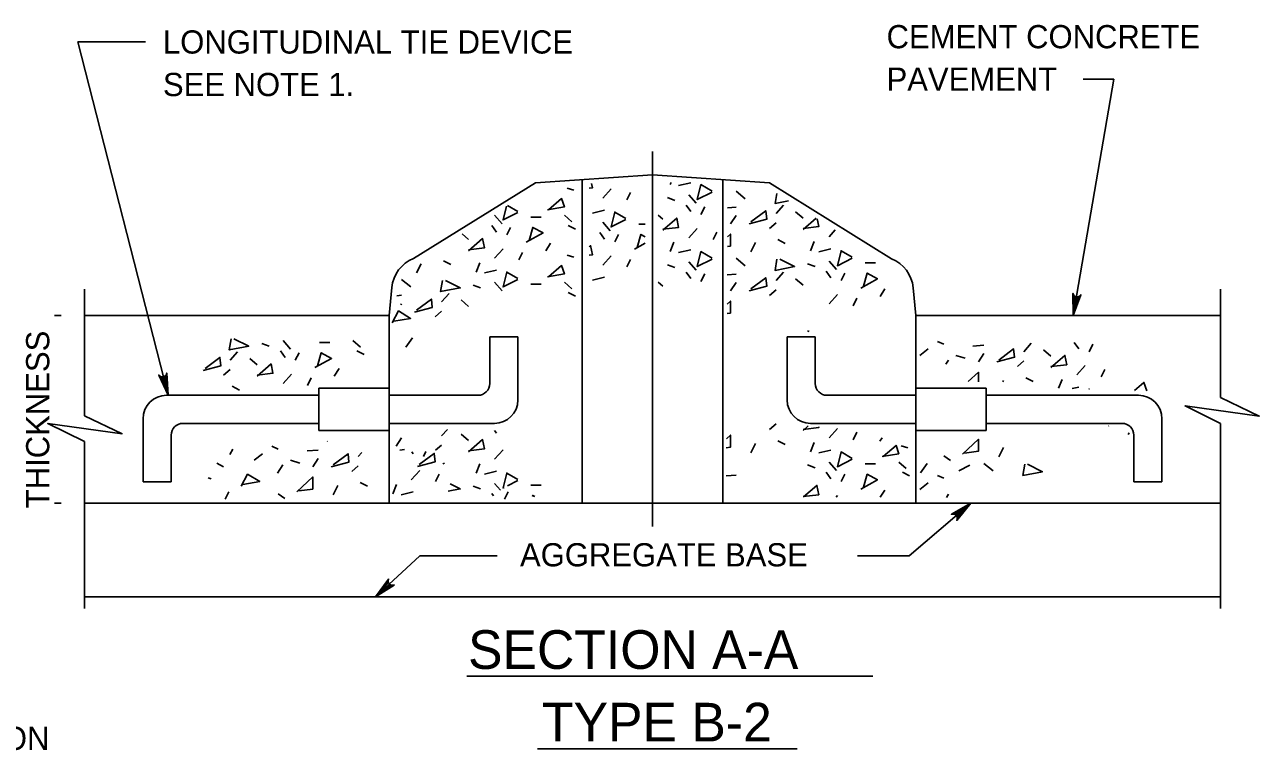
# Model space of a CAD drawing. Extents: x -7.6 to -0.4, y 98.1 to 108.3.
# Drawn here: x -3.651 to -0.457, y 106.268 to 108.145 of the extents above; entities that cross this region are included whole.
import ezdxf

# ---------------------------------------------------------------- set-up
doc = ezdxf.new("R2010")
doc.units = 0
for name, color, linetype in [('DETL-DIMS', 7, 'Continuous'), ('DETL-LINE', 7, 'Continuous'), ('DETL-NOTE', 7, 'Continuous'), ('DETL-PATT', 7, 'Continuous'), ('DETL-TITL', 7, 'Continuous')]:
    doc.layers.add(name, color=color, linetype=linetype)

msp = doc.modelspace()

# ---------------------------------------------------------------- linework, layer by layer
at = {"layer": 'DETL-DIMS'}
for p, q in [((-3.5134, 108.1001), (-3.2795, 107.1864)), ((-3.5134, 108.1001), (-3.3386, 108.1001)), ((-0.833, 108.0038), (-0.9381, 107.3925)), ((-0.9126, 108.0038), (-0.833, 108.0038)), ((-2.0265, 106.847), (-2.0265, 107.8167)), ((-3.5567, 107.3925), (-3.5738, 107.3925)), ((-3.5738, 106.9076), (-3.5567, 106.9076)), ((-1.3625, 106.771), (-1.2032, 106.9076)), ((-2.6289, 106.771), (-2.7435, 106.6652)), ((-2.428, 106.771), (-2.6289, 106.771)), ((-1.4964, 106.771), (-1.3625, 106.771))]:
    msp.add_line(p, q, dxfattribs=at)
for points in [[(-0.9381, 107.3925), (-0.9389, 107.45), (-0.9367, 107.4452), (-0.9334, 107.4423), (-0.9297, 107.441), (-0.9259, 107.441), (-0.9218, 107.4426), (-0.9181, 107.4464), (-0.9381, 107.3925), (-0.9218, 107.4426), (-0.9259, 107.441), (-0.9381, 107.3925), (-0.9297, 107.441), (-0.9334, 107.4423), (-0.9381, 107.3925), (-0.9367, 107.4452)], [(-3.2795, 107.1864), (-3.3038, 107.2385), (-3.2998, 107.2351), (-3.2955, 107.2338), (-3.2917, 107.2341), (-3.2882, 107.2357), (-3.2851, 107.2388), (-3.2832, 107.2438), (-3.2795, 107.1864), (-3.2851, 107.2388), (-3.2882, 107.2357), (-3.2795, 107.1864), (-3.2917, 107.2341), (-3.2955, 107.2338), (-3.2795, 107.1864), (-3.2998, 107.2351)], [(-1.2032, 106.9076), (-1.2392, 106.8628), (-1.2379, 106.8679), (-1.2387, 106.8723), (-1.2406, 106.8756), (-1.2436, 106.878), (-1.2477, 106.8794), (-1.253, 106.8789), (-1.2032, 106.9076), (-1.2477, 106.8794), (-1.2436, 106.878), (-1.2032, 106.9076), (-1.2406, 106.8756), (-1.2387, 106.8723), (-1.2032, 106.9076), (-1.2379, 106.8679)], [(-2.7435, 106.6652), (-2.7092, 106.7113), (-2.7104, 106.7062), (-2.7094, 106.7018), (-2.7073, 106.6986), (-2.7043, 106.6963), (-2.7001, 106.695), (-2.6948, 106.6958), (-2.7435, 106.6652), (-2.7001, 106.695), (-2.7043, 106.6963), (-2.7435, 106.6652), (-2.7073, 106.6986), (-2.7094, 106.7018), (-2.7435, 106.6652), (-2.7104, 106.7062)]]:
    msp.add_lwpolyline(points, dxfattribs=at)
at = {"layer": 'DETL-LINE'}
for p, q in [((-2.3295, 107.7359), (-2.0265, 107.7561)), ((-2.2083, 106.9076), (-2.2083, 107.744)), ((-1.7235, 107.7359), (-2.0265, 107.7561)), ((-1.8447, 106.9076), (-1.8447, 107.744)), ((-2.3295, 107.7359), (-2.645, 107.5404)), ((-1.7235, 107.7359), (-1.4079, 107.5396)), ((-3.4961, 107.4608), (-3.4961, 107.1332)), ((-2.7082, 107.3925), (-2.701, 107.4653)), ((-1.3448, 107.3925), (-1.352, 107.4645)), ((-0.5569, 107.4608), (-0.5569, 107.1804)), ((-3.4961, 107.3925), (-2.7082, 107.3925)), ((-2.7082, 107.3925), (-2.7082, 106.9076)), ((-1.3448, 107.3925), (-0.5569, 107.3925)), ((-1.3448, 107.3925), (-1.3448, 106.9076)), ((-2.4476, 107.3379), (-2.4476, 107.2167)), ((-2.4476, 107.3379), (-2.3749, 107.3379)), ((-2.3749, 107.3379), (-2.3749, 107.1743)), ((-1.6781, 107.3379), (-1.6781, 107.1743)), ((-1.6054, 107.3379), (-1.6781, 107.3379)), ((-1.6054, 107.3379), (-1.6054, 107.2167)), ((-2.7082, 107.2046), (-2.8901, 107.2046)), ((-2.8901, 107.2046), (-2.8901, 107.0955)), ((-1.3448, 107.2228), (-1.3448, 107.0773)), ((-1.3448, 107.2046), (-1.163, 107.2046)), ((-1.163, 107.2046), (-1.163, 107.0955)), ((-3.284, 107.1864), (-2.8901, 107.1864)), ((-2.7082, 107.1864), (-2.4779, 107.1864)), ((-1.3448, 107.1864), (-1.5751, 107.1864)), ((-0.769, 107.1864), (-1.163, 107.1864)), ((-3.3446, 107.1258), (-3.3446, 106.9622)), ((-3.2416, 107.1137), (-2.8901, 107.1137)), ((-2.7082, 107.1137), (-2.4355, 107.1137)), ((-1.3448, 107.1137), (-1.6175, 107.1137)), ((-0.8115, 107.1137), (-1.163, 107.1137)), ((-0.7084, 107.1258), (-0.7084, 106.9622)), ((-0.5569, 107.1138), (-0.5569, 106.6353)), ((-3.2719, 107.0834), (-3.2719, 106.9622)), ((-2.7082, 107.0955), (-2.8901, 107.0955)), ((-1.3448, 107.0955), (-1.163, 107.0955)), ((-0.7812, 107.0834), (-0.7812, 106.9622)), ((-3.4961, 107.0666), (-3.4961, 106.6353)), ((-2.7082, 107.0289), (-2.7082, 106.9076)), ((-1.3448, 107.0289), (-1.3448, 106.9076)), ((-3.3446, 106.9622), (-3.2719, 106.9622)), ((-0.7084, 106.9622), (-0.7812, 106.9622)), ((-3.4961, 106.9076), (-0.5569, 106.9076)), ((-3.4961, 106.6652), (-0.5569, 106.6652))]:
    msp.add_line(p, q, dxfattribs=at)
for points in [[(-0.5569, 107.1138), (-0.6488, 107.1588), (-0.4566, 107.1326), (-0.5569, 107.1804)], [(-3.4961, 107.0666), (-3.5913, 107.1131), (-3.399, 107.087), (-3.4961, 107.1332)]]:
    msp.add_lwpolyline(points, dxfattribs=at)
for centre, radius, start, end in [((-2.6105, 107.4562), 0.0909, 112.2917, 174.2894), ((-1.4425, 107.4555), 0.0909, 5.7107, 67.6341), ((-2.4779, 107.2167), 0.0303, 270, 0), ((-1.5751, 107.2167), 0.0303, 180, 270), ((-3.284, 107.1258), 0.0606, 90, 180), ((-2.4355, 107.1743), 0.0606, 270, 0), ((-1.6175, 107.1743), 0.0606, 180, 270), ((-0.769, 107.1258), 0.0606, 0, 90), ((-3.2416, 107.0834), 0.0303, 90, 180), ((-0.8115, 107.0834), 0.0303, 0, 90)]:
    msp.add_arc(centre, radius, start, end, dxfattribs=at)
at = {"layer": 'DETL-PATT'}
for p, q in [((-2.2472, 107.7217), (-2.2304, 107.7169)), ((-2.1337, 107.7204), (-2.1553, 107.6963)), ((-2.0831, 107.7108), (-2.0928, 107.6915)), ((-1.9785, 107.7364), (-1.9806, 107.7312)), ((-1.9276, 107.736), (-1.9589, 107.7288)), ((-1.8104, 107.7141), (-1.7864, 107.6948)), ((-1.9878, 107.6975), (-1.9685, 107.6903)), ((-1.9397, 107.6783), (-1.9276, 107.6614)), ((-1.9324, 107.7047), (-1.9132, 107.6831)), ((-1.7069, 107.6563), (-1.6877, 107.6779)), ((-2.435, 107.6519), (-2.4157, 107.6302)), ((-2.4014, 107.6771), (-2.3748, 107.6615)), ((-2.3411, 107.6471), (-2.3146, 107.6471)), ((-2.2545, 107.6519), (-2.2352, 107.6351)), ((-2.1505, 107.665), (-2.1818, 107.6578)), ((-2.0117, 107.6526), (-1.9998, 107.6422)), ((-1.8915, 107.6734), (-1.9012, 107.6542)), ((-1.8322, 107.6713), (-1.8104, 107.6731)), ((-1.8249, 107.6298), (-1.8104, 107.6515)), ((-1.6564, 107.6611), (-1.6371, 107.6443)), ((-2.4422, 107.6254), (-2.4302, 107.6086)), ((-2.3941, 107.6206), (-2.4037, 107.6014)), ((-2.2448, 107.6254), (-2.2256, 107.6158)), ((-2.1553, 107.6337), (-2.1361, 107.6121)), ((-2.0615, 107.6289), (-2.0454, 107.6289)), ((-1.9108, 107.6181), (-1.9324, 107.594)), ((-1.7238, 107.6178), (-1.7069, 107.6322)), ((-1.6032, 107.6448), (-1.6371, 107.6154)), ((-1.5537, 107.6139), (-1.5697, 107.5961)), ((-2.5187, 107.6036), (-2.5024, 107.5893)), ((-2.1625, 107.6073), (-2.1505, 107.5904)), ((-2.1144, 107.6024), (-2.124, 107.5832)), ((-1.9709, 107.582), (-1.9806, 107.5579)), ((-1.8602, 107.6085), (-1.8699, 107.5892)), ((-1.7021, 107.5889), (-1.6829, 107.5793)), ((-1.6082, 107.5841), (-1.6179, 107.56)), ((-2.4133, 107.5653), (-2.435, 107.5412)), ((-2.3628, 107.5556), (-2.3724, 107.5364)), ((-2.3026, 107.5604), (-2.2906, 107.5797)), ((-2.0735, 107.5639), (-2.0454, 107.5796)), ((-1.9276, 107.5627), (-1.9589, 107.5555)), ((-1.7719, 107.5576), (-1.7599, 107.5817)), ((-1.5649, 107.5648), (-1.5962, 107.5576)), ((-2.6372, 107.5027), (-2.6251, 107.5267)), ((-2.5674, 107.534), (-2.5481, 107.5243)), ((-2.4735, 107.5292), (-2.4831, 107.5051)), ((-2.2472, 107.5484), (-2.2304, 107.5436)), ((-2.1337, 107.5471), (-2.1553, 107.523)), ((-2.0831, 107.5375), (-2.0928, 107.5182)), ((-1.9878, 107.5242), (-1.9685, 107.517)), ((-1.9324, 107.5314), (-1.9132, 107.5098)), ((-1.8104, 107.5408), (-1.7864, 107.5215)), ((-1.6251, 107.5263), (-1.6058, 107.5191)), ((-1.5697, 107.5336), (-1.5505, 107.5119)), ((-1.4759, 107.5287), (-1.4494, 107.5287)), ((-2.4302, 107.5099), (-2.4615, 107.5027)), ((-2.1505, 107.4917), (-2.1818, 107.4845)), ((-1.9397, 107.505), (-1.9276, 107.4881)), ((-1.8915, 107.5002), (-1.9012, 107.4809)), ((-1.8331, 107.4979), (-1.8104, 107.4998)), ((-1.7069, 107.483), (-1.6877, 107.5047)), ((-1.6564, 107.4878), (-1.6371, 107.471)), ((-1.5769, 107.5071), (-1.5649, 107.4902)), ((-1.5288, 107.5023), (-1.5384, 107.483)), ((-2.6757, 107.4858), (-2.6516, 107.4666)), ((-2.4903, 107.4714), (-2.4711, 107.4642)), ((-2.435, 107.4786), (-2.4157, 107.4569)), ((-2.3411, 107.4738), (-2.3146, 107.4738)), ((-2.2545, 107.4786), (-2.2352, 107.4618)), ((-2.0117, 107.4792), (-1.9998, 107.4689)), ((-1.8249, 107.4565), (-1.8104, 107.4782)), ((-1.7238, 107.4445), (-1.7069, 107.4589)), ((-1.4374, 107.4421), (-1.4253, 107.4613)), ((-2.6884, 107.4438), (-2.6757, 107.4449)), ((-2.6774, 107.4206), (-2.6757, 107.4232)), ((-2.5722, 107.4281), (-2.5529, 107.4497)), ((-2.5216, 107.4329), (-2.5024, 107.416)), ((-2.2448, 107.4521), (-2.2256, 107.4425)), ((-1.5481, 107.4469), (-1.5697, 107.4228)), ((-1.4975, 107.4373), (-1.5072, 107.418)), ((-2.589, 107.3896), (-2.5722, 107.404)), ((-2.982, 107.3277), (-2.9628, 107.306)), ((-2.8015, 107.3277), (-2.7823, 107.3108)), ((-2.6475, 107.3349), (-2.6643, 107.3108)), ((-1.6251, 107.353), (-1.6209, 107.3514)), ((-3.1192, 107.2771), (-3.1, 107.2988)), ((-3.0374, 107.3204), (-3.0181, 107.3132)), ((-2.9893, 107.3012), (-2.9772, 107.2843)), ((-2.9411, 107.2964), (-2.9507, 107.2771)), ((-2.8882, 107.3228), (-2.8617, 107.3228)), ((-2.7919, 107.3012), (-2.7726, 107.2916)), ((-1.3135, 107.3064), (-1.3352, 107.2896)), ((-1.2894, 107.3257), (-1.2726, 107.3184)), ((-1.198, 107.3136), (-1.1691, 107.316)), ((-1.0656, 107.2992), (-1.0464, 107.3208)), ((-1.0151, 107.304), (-0.9958, 107.2872)), ((-0.9356, 107.3233), (-0.9236, 107.3064)), ((-0.8875, 107.3184), (-0.8971, 107.2992)), ((-3.0687, 107.2819), (-3.0494, 107.2651)), ((-1.2606, 107.2775), (-1.2678, 107.2666)), ((-1.2413, 107.2896), (-1.2172, 107.2823)), ((-1.1835, 107.2727), (-1.1691, 107.2944)), ((-1.0825, 107.2607), (-1.0656, 107.2751)), ((-0.9068, 107.2631), (-0.9284, 107.239)), ((-3.1361, 107.2386), (-3.1192, 107.2531)), ((-2.9604, 107.241), (-2.982, 107.2169)), ((-2.9098, 107.2314), (-2.9194, 107.2121)), ((-2.8497, 107.2362), (-2.8376, 107.2554)), ((-1.0608, 107.2318), (-1.0415, 107.2222)), ((-0.8562, 107.2534), (-0.8658, 107.2342)), ((-3.1144, 107.2097), (-3.0952, 107.2001)), ((-1.1203, 107.221), (-1.1186, 107.2246)), ((-0.9669, 107.227), (-0.9758, 107.2048)), ((-0.9236, 107.2077), (-0.9406, 107.2038)), ((-1.7238, 107.0979), (-1.7069, 107.1123)), ((-1.6238, 107.1071), (-1.6371, 107.0955)), ((-0.8466, 107.1066), (-0.8458, 107.1071)), ((-2.6901, 107.055), (-2.6757, 107.0767)), ((-2.5722, 107.0815), (-2.5573, 107.0982)), ((-2.5216, 107.0863), (-2.5024, 107.0694)), ((-2.435, 107.0955), (-2.4302, 107.0887)), ((-1.5481, 107.1003), (-1.5697, 107.0762)), ((-1.4975, 107.0907), (-1.5072, 107.0714)), ((-1.4383, 107.0677), (-1.4326, 107.0768)), ((-0.796, 107.085), (-0.7933, 107.0893)), ((-3.1198, 107.0329), (-3.112, 107.0467)), ((-3.0115, 107.0546), (-2.9947, 107.0474)), ((-2.9201, 107.0426), (-2.8912, 107.0449)), ((-2.8683, 107.0676), (-2.8671, 107.0666)), ((-2.68, 107.0449), (-2.6683, 107.0459)), ((-2.6492, 107.0402), (-2.6457, 107.0353)), ((-2.6129, 107.0408), (-2.6192, 107.0281)), ((-2.5876, 107.0442), (-2.5722, 107.0574)), ((-2.4133, 107.0454), (-2.435, 107.0213)), ((-1.7719, 107.0377), (-1.7599, 107.0618)), ((-1.7021, 107.069), (-1.6829, 107.0594)), ((-1.6082, 107.0642), (-1.6179, 107.0401)), ((-1.5649, 107.0449), (-1.5962, 107.0377)), ((-1.3829, 107.0556), (-1.3661, 107.0508)), ((-1.1306, 107.0272), (-1.1186, 107.0513)), ((-3.1535, 107.0113), (-3.1367, 107.0016)), ((-3.0356, 107.0353), (-3.0573, 107.0185)), ((-2.9634, 107.0185), (-2.9393, 107.0113)), ((-2.9056, 107.0016), (-2.8912, 107.0233)), ((-2.7877, 107.0281), (-2.7788, 107.0382)), ((-2.5687, 107.0089), (-2.5644, 107.0112)), ((-2.4735, 107.0093), (-2.4831, 106.9852)), ((-1.5697, 107.0137), (-1.5505, 106.992)), ((-1.4759, 107.0088), (-1.4494, 107.0088)), ((-1.3892, 107.0137), (-1.37, 106.9968)), ((-1.3159, 107.0104), (-1.3328, 106.9863)), ((-1.2726, 107.0296), (-1.2558, 107.0176)), ((-1.1691, 107.0104), (-1.145, 106.9911)), ((-2.9827, 107.0064), (-2.9971, 106.9848)), ((-2.8045, 106.9896), (-2.7877, 107.004)), ((-2.6288, 106.992), (-2.6505, 106.9679)), ((-2.5783, 106.9824), (-2.5879, 106.9631)), ((-2.4302, 106.99), (-2.4615, 106.9828)), ((-1.8359, 106.9778), (-1.8104, 106.98)), ((-1.6251, 107.0064), (-1.6058, 106.9992)), ((-1.5769, 106.9872), (-1.5649, 106.9703)), ((-1.5288, 106.9824), (-1.5384, 106.9631)), ((-1.3796, 106.9872), (-1.3618, 106.9783)), ((-1.2894, 106.9791), (-1.2726, 106.9718)), ((-1.2052, 107.0056), (-1.2341, 106.9911)), ((-3.1762, 106.9727), (-3.168, 106.9703)), ((-2.8527, 106.9294), (-2.8407, 106.9535)), ((-2.7829, 106.9607), (-2.7636, 106.9511)), ((-2.689, 106.9559), (-2.6986, 106.9318)), ((-2.4903, 106.9515), (-2.4711, 106.9443)), ((-2.435, 106.9587), (-2.4194, 106.9412)), ((-2.3748, 106.9659), (-2.4015, 106.9526)), ((-2.3411, 106.9539), (-2.3146, 106.9539)), ((-1.3135, 106.9598), (-1.3352, 106.943)), ((-3.1319, 106.9174), (-3.1223, 106.9367)), ((-2.9947, 106.9318), (-2.9778, 106.9198)), ((-2.6457, 106.9367), (-2.677, 106.9294)), ((-2.4422, 106.9322), (-2.4383, 106.9268)), ((-2.4098, 106.9174), (-2.4002, 106.9367)), ((-1.5481, 106.927), (-1.5516, 106.9231)), ((-1.4371, 106.9226), (-1.4253, 106.9414)), ((-1.2606, 106.9309), (-1.2663, 106.9223))]:
    msp.add_line(p, q, dxfattribs=at)
for points in [[(-2.1904, 107.7218), (-2.1818, 107.7228), (-2.1841, 107.7343)], [(-1.8723, 107.7119), (-1.9108, 107.6927), (-1.9012, 107.7312), (-1.8723, 107.7144)], [(-2.2978, 107.6663), (-2.2545, 107.6736), (-2.2617, 107.6952), (-2.2954, 107.6663)], [(-1.705, 107.7084), (-1.7093, 107.6828), (-1.6746, 107.6894)], [(-2.3748, 107.6591), (-2.4133, 107.6399), (-2.4045, 107.6751)], [(-2.0952, 107.641), (-2.1337, 107.6217), (-2.124, 107.6602), (-2.0952, 107.6434)], [(-1.7767, 107.6298), (-1.731, 107.6418), (-1.7334, 107.6635), (-1.7719, 107.6346)], [(-2.3532, 107.5821), (-2.3098, 107.6062), (-2.3363, 107.6206), (-2.3459, 107.5869)], [(-1.9998, 107.6157), (-1.9589, 107.6205), (-1.9637, 107.6446), (-1.9998, 107.6133)], [(-1.6371, 107.6178), (-1.5962, 107.6226), (-1.6003, 107.643)], [(-2.5024, 107.5628), (-2.4615, 107.5677), (-2.4663, 107.5917), (-2.5024, 107.5604)], [(-2.0454, 107.5963), (-2.0567, 107.6024), (-2.0663, 107.5688)], [(-1.8327, 107.571), (-1.8249, 107.5721), (-1.8249, 107.6033), (-1.8326, 107.5961)], [(-2.1904, 107.5485), (-2.1818, 107.5495), (-2.1866, 107.5736), (-2.1904, 107.5703)], [(-1.8723, 107.5387), (-1.9108, 107.5194), (-1.9012, 107.5579), (-1.8723, 107.5411)], [(-1.5096, 107.5408), (-1.5481, 107.5215), (-1.5384, 107.56), (-1.5096, 107.5432)], [(-2.2978, 107.4931), (-2.2545, 107.5003), (-2.2617, 107.5219), (-2.2954, 107.4931)], [(-1.7045, 107.5384), (-1.7093, 107.5095), (-1.6588, 107.5191), (-1.6973, 107.5384)], [(-2.3748, 107.4858), (-2.4133, 107.4666), (-2.4037, 107.5051), (-2.3748, 107.4882)], [(-1.7767, 107.4565), (-1.731, 107.4686), (-1.7334, 107.4902), (-1.7719, 107.4613)], [(-1.4879, 107.4637), (-1.4446, 107.4878), (-1.471, 107.5023), (-1.4807, 107.4686)], [(-2.5698, 107.4834), (-2.5746, 107.4545), (-2.524, 107.4642), (-2.5625, 107.4834)], [(-2.642, 107.4016), (-2.5962, 107.4136), (-2.5987, 107.4353), (-2.6372, 107.4064)], [(-1.8337, 107.3976), (-1.8249, 107.3988), (-1.8249, 107.4301), (-1.8335, 107.4219)], [(-2.7004, 107.3734), (-2.6836, 107.4047), (-2.6523, 107.3854), (-2.6956, 107.3782)], [(-3.1168, 107.3325), (-3.1216, 107.3036), (-3.0711, 107.3132), (-3.1096, 107.3325)], [(-2.9002, 107.2579), (-2.8569, 107.2819), (-2.8834, 107.2964), (-2.893, 107.2627)], [(-1.1354, 107.2727), (-1.0897, 107.2847), (-1.0921, 107.3064), (-1.1306, 107.2775)], [(-3.189, 107.2506), (-3.1433, 107.2627), (-3.1457, 107.2843), (-3.1842, 107.2554)], [(-3.0494, 107.2386), (-3.0085, 107.2434), (-3.0133, 107.2675), (-3.0494, 107.2362)], [(-0.9958, 107.2607), (-0.9549, 107.2655), (-0.9597, 107.2896), (-0.9958, 107.2583)], [(-1.1835, 107.221), (-1.1835, 107.2462), (-1.2094, 107.2219)], [(-0.8972, 107.2025), (-0.8971, 107.2029), (-0.8964, 107.2025)], [(-0.7479, 107.1982), (-0.7551, 107.2198), (-0.7792, 107.1991)], [(-1.6371, 107.0979), (-1.5962, 107.1027), (-1.5966, 107.1048)], [(-2.5024, 107.043), (-2.4615, 107.0478), (-2.4663, 107.0718), (-2.5024, 107.0406)], [(-1.8355, 107.0508), (-1.8249, 107.0522), (-1.8249, 107.0834), (-1.8354, 107.0736)], [(-1.2197, 107.0368), (-1.1835, 107.0417), (-1.1835, 107.0729), (-1.2245, 107.0344)], [(-1.5096, 107.0209), (-1.5481, 107.0016), (-1.5384, 107.0401), (-1.5096, 107.0233)], [(-1.4325, 107.0281), (-1.3892, 107.0353), (-1.3964, 107.057), (-1.4301, 107.0281)], [(-2.8575, 107.0016), (-2.8118, 107.0137), (-2.8142, 107.0353), (-2.8527, 107.0064)], [(-2.6346, 107.0026), (-2.5889, 107.0146), (-2.5913, 107.0363), (-2.6298, 107.0074)], [(-1.0632, 107.0079), (-1.068, 106.9791), (-1.0175, 106.9887), (-1.056, 107.0079)], [(-3.091, 106.9511), (-3.0741, 106.9824), (-3.0428, 106.9631), (-3.0862, 106.9559)], [(-2.9417, 106.9391), (-2.9056, 106.9439), (-2.9056, 106.9752), (-2.9465, 106.9367)], [(-2.41, 106.9484), (-2.4133, 106.9467), (-2.4037, 106.9852), (-2.3748, 106.9683)], [(-1.4879, 106.9439), (-1.4446, 106.9679), (-1.471, 106.9824), (-1.4807, 106.9487)], [(-2.555, 106.9384), (-2.524, 106.9443), (-2.5504, 106.9575)], [(-1.6371, 106.9246), (-1.5962, 106.9294), (-1.601, 106.9535), (-1.6356, 106.9235)], [(-2.331, 106.9246), (-2.3363, 106.9274), (-2.337, 106.9248)]]:
    msp.add_lwpolyline(points, dxfattribs=at)
at = {"layer": 'DETL-TITL'}
for p, q in [((-2.5067, 106.4603), (-1.4566, 106.4603)), ((-2.3243, 106.2726), (-1.6522, 106.2726))]:
    msp.add_line(p, q, dxfattribs=at)

# ---------------------------------------------------------------- texts
at = {"layer": 'DETL-NOTE'}
for s, p in [('LONGITUDINAL TIE DEVICE', (-3.2931, 108.0701)), ('CEMENT CONCRETE', (-1.4209, 108.0838)), ('PAVEMENT', (-1.4209, 107.9738)), ('SEE NOTE 1.', (-3.2931, 107.9601)), ('AGGREGATE BASE', (-2.3693, 106.744)), ('PROPOSED PAVING SECTION', (-4.746, 106.2693))]:
    msp.add_text(s, height=0.06, dxfattribs=at).set_placement(p)
msp.add_text('THICKNESS', height=0.06, rotation=90, dxfattribs=at).set_placement((-3.5872, 106.8943))
at = {"layer": 'DETL-TITL'}
for s, p in [('SECTION A-A', (-2.5037, 106.4789)), ('TYPE B-2', (-2.3124, 106.2912))]:
    msp.add_text(s, height=0.1, dxfattribs=at).set_placement(p)

doc.saveas('drawing.dxf')
